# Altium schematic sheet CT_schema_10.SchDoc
size 387 x 278 mm
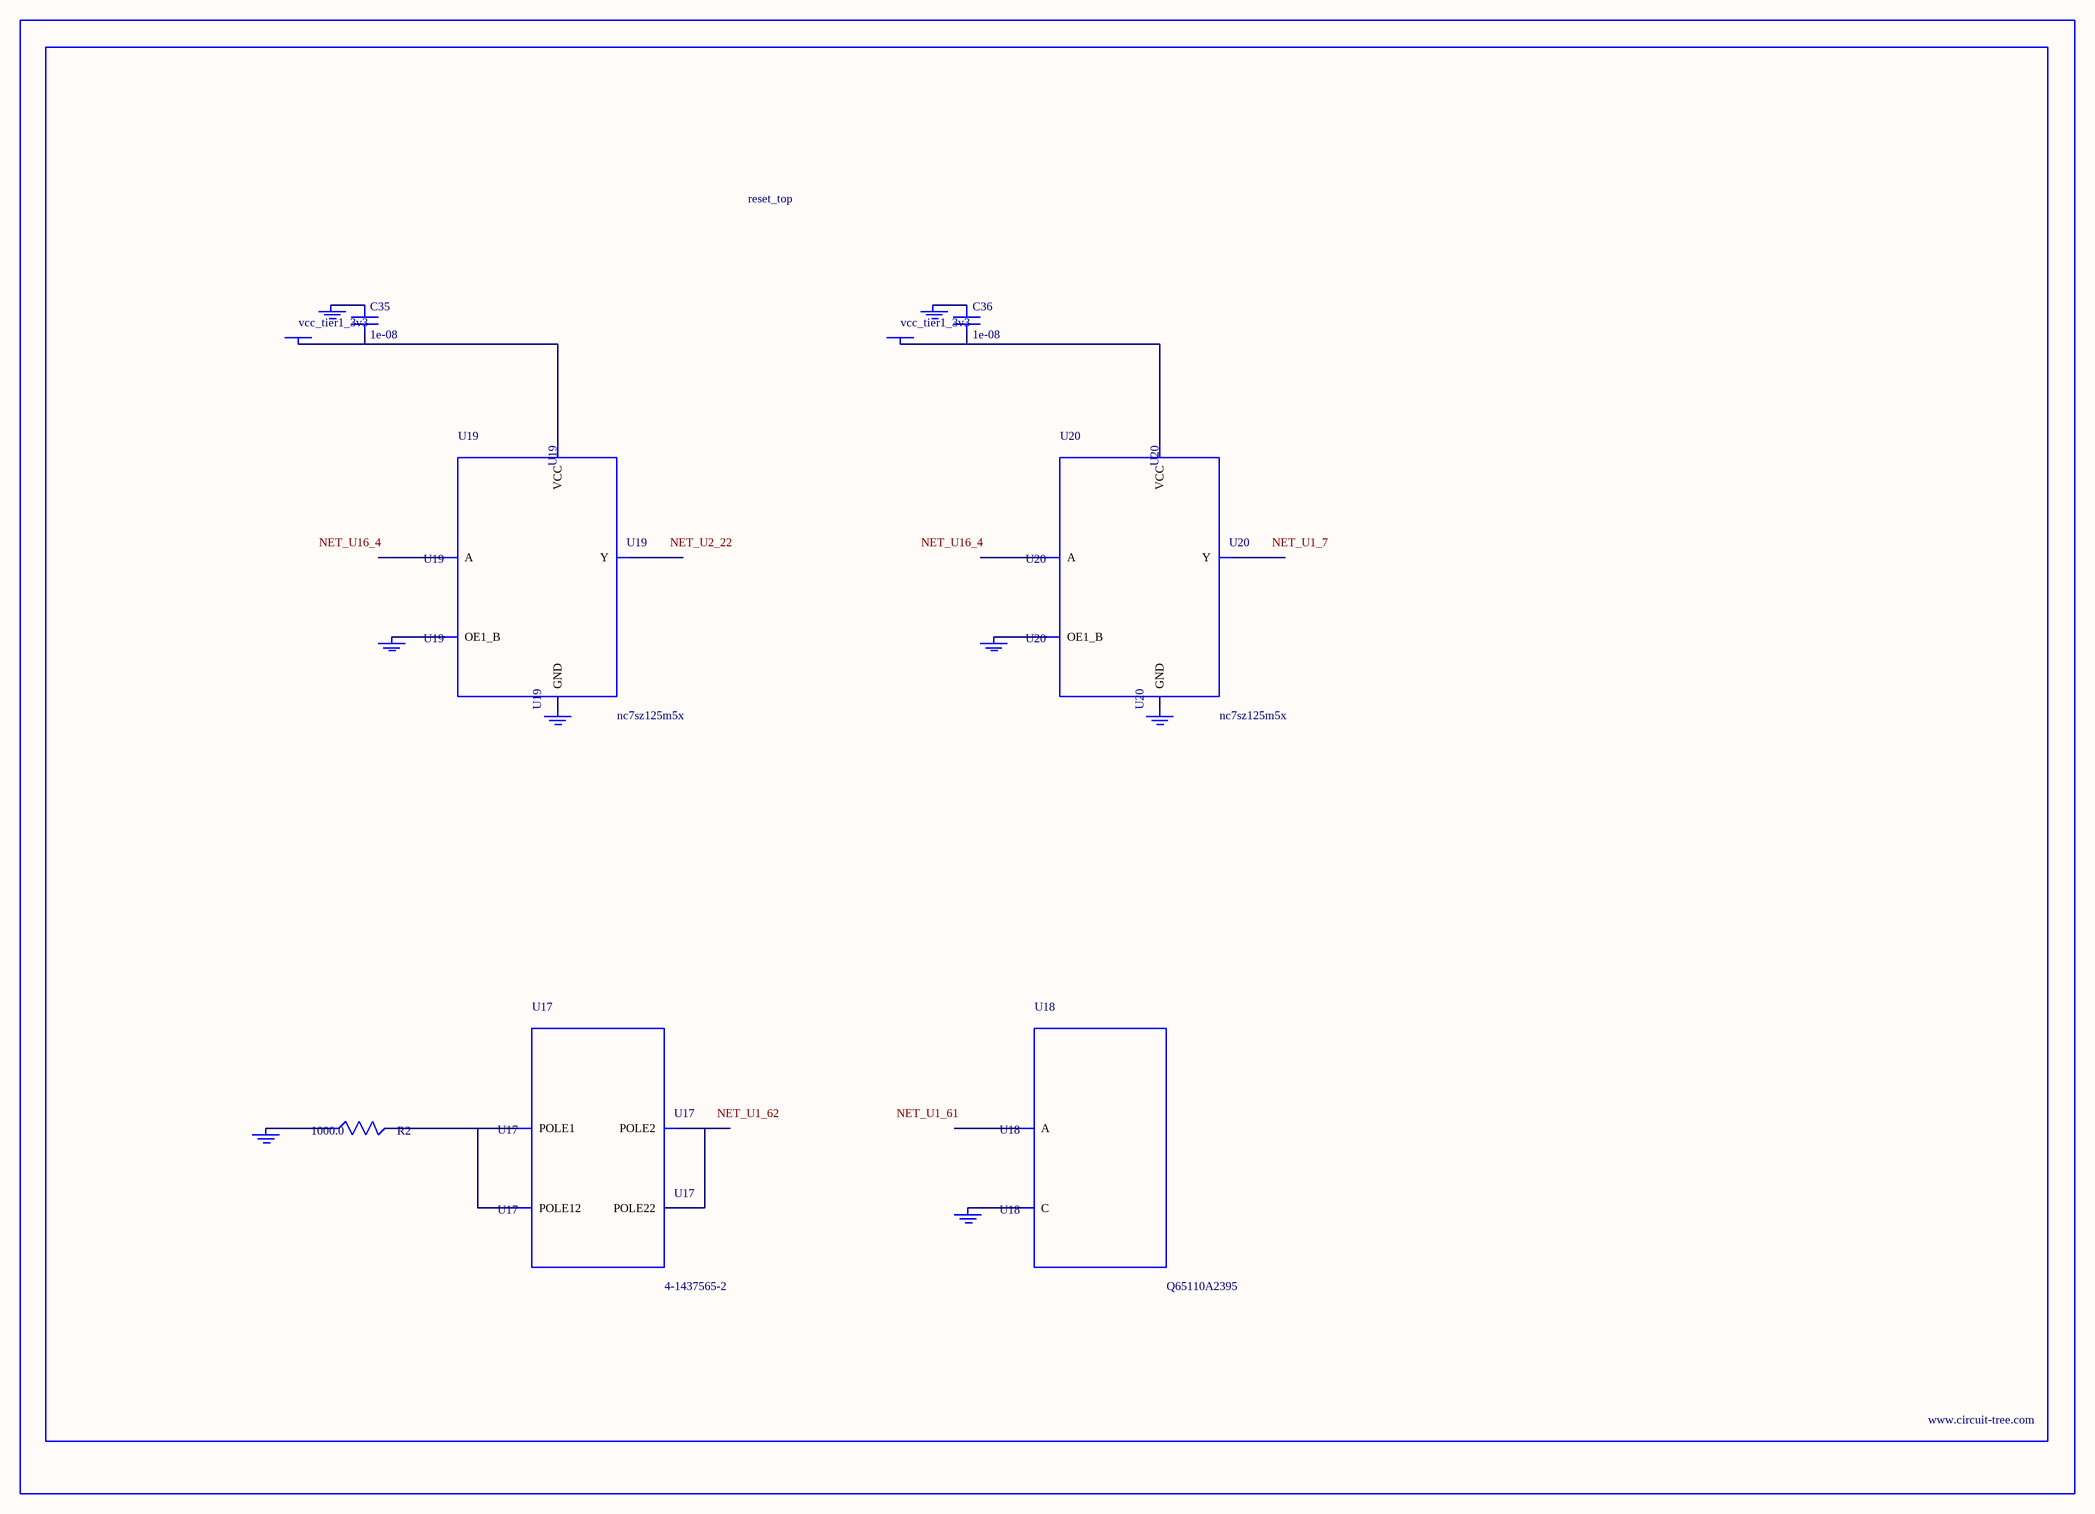
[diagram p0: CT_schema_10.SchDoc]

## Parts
BORDER9  (no value)
C35  1e-08  [C0402]
C36  1e-08  [C0402]
GND_INSTANCE_9_0  (no value)
GND_INSTANCE_9_1  (no value)
GND_INSTANCE_9_2  (no value)
GND_INSTANCE_9_3  (no value)
GND_INSTANCE_9_4  (no value)
GND_INSTANCE_9_5  (no value)
GND_INSTANCE_9_6  (no value)
GND_INSTANCE_9_7  (no value)
POWER_INSTANCE_9_0  vcc_tier1_3v3
POWER_INSTANCE_9_1  vcc_tier1_3v3
R2  1000.0  [R0603]
U17  4-1437565-2  [SW_4-1437565-2]
U18  Q65110A2395  [LGM67K-G1J2-24-Z]
U19  nc7sz125m5x  [NC7SZ125M5X]
U20  nc7sz125m5x  [NC7SZ125M5X]

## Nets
NetC35_1: C35.1 GND_INSTANCE_9_2.0(GND)
NetC35_2: C35.2 POWER_INSTANCE_9_0.0(PWR) U19.5(VCC)
NetC36_1: C36.1 GND_INSTANCE_9_5.0(GND)
NetC36_2: C36.2 POWER_INSTANCE_9_1.0(PWR) U20.5(VCC)
NetGND_INSTANCE_9_0_0: GND_INSTANCE_9_0.0(GND) R2.1
NetGND_INSTANCE_9_1_0: GND_INSTANCE_9_1.0(GND) U18.C
NetGND_INSTANCE_9_3_0: GND_INSTANCE_9_3.0(GND) U19.1(OE1_B)
NetGND_INSTANCE_9_4_0: GND_INSTANCE_9_4.0(GND) U19.3(GND)
NetGND_INSTANCE_9_6_0: GND_INSTANCE_9_6.0(GND) U20.1(OE1_B)
NetGND_INSTANCE_9_7_0: GND_INSTANCE_9_7.0(GND) U20.3(GND)
NetR2_2: R2.2 U17.1(POLE1) U17.2(POLE12)
NetU17_3: U17.3(POLE2) U17.4(POLE22)

Not connected (* = marked no-connect by the designer): U18 A; U19 2(A) 4(Y); U20 2(A) 4(Y)

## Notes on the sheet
- Labels drawn without touching a wire or pin: NET_U1_7, NET_U1_61, NET_U1_62, NET_U2_22, NET_U16_4

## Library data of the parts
BORDER9 = BORDER_PAGE9
C35 C36 = C0402C103K3RAC
GND_INSTANCE_9_0-GND_INSTANCE_9_7 = GND
POWER_INSTANCE_9_0 POWER_INSTANCE_9_1 = PWR
R2 = RC0603JR-071KL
